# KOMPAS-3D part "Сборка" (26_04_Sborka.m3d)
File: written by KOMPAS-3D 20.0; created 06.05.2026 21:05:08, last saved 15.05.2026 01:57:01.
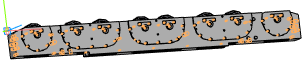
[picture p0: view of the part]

Document properties: Автор: taras; Полное имя файла: E:\test_kompas\all_v18\26_04_Sborka.m3d

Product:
- Part/product: Сборка
    Масса: 400.156
  - Component [standard]: Винт М12-6gx20 ГОСТ 11738-84  | qty 16  | pos. 31  | Масса: 0.03416; Раздел спецификации: Стандартные изделия; Рассекать на разрезах: no
  - Component [standard]: Болт М16-6gx170 ГОСТ 7795-70  | qty 6  | pos. 30  | Масса: 0.2633; Раздел спецификации: Стандартные изделия; Рассекать на разрезах: no
  - Component [standard]: Подшипник 318 ГОСТ 8338-75  | qty 7  | pos. 29  | Масса: 4.954; Раздел спецификации: Стандартные изделия; additional columns: 318
  - Component [detail]: Деталь  | pos. 28  | Масса: 0.134151; source file: ..\all_v22\Planka_rigelnaya (1).m3d
  - Component [detail]: Деталь  | pos. 27  | Масса: 0.134151; source file: ..\all_v22\Planka_rigelnaya (1).m3d
  - Component [detail]: Деталь  | pos. 26  | Масса: 0.134151; source file: ..\all_v22\Planka_rigelnaya (1).m3d
  - Component [detail]: Деталь  | pos. 25  | Масса: 0.134151; source file: ..\all_v22\Planka_rigelnaya (1).m3d
  - Component [detail]: Деталь  | pos. 24  | Масса: 0.134151; source file: ..\all_v22\Planka_rigelnaya (1).m3d
  - Component [detail]: Деталь  | pos. 23  | Масса: 0.134151; source file: ..\all_v22\Planka_rigelnaya (1).m3d
  - Component [detail]: Деталь  | pos. 22  | Масса: 0.134151; source file: ..\all_v22\Planka_rigelnaya (1).m3d
  - Component [detail]: Деталь  | pos. 21  | Масса: 0.134151; source file: ..\all_v22\Planka_rigelnaya (1).m3d
  - Component [detail]: Деталь  | pos. 20  | Масса: 2.04624; source file: ..\all_v22\Planka_rigelnaya (1).m3d
  - Component [detail]: Деталь  | pos. 19  | Масса: 2.04624; source file: ..\all_v22\Planka_rigelnaya (1).m3d
  - Component [standard]: Винт М10-6gx20 ГОСТ 11738-84  | qty 31  | pos. 17  | Масса: 0.02351; Раздел спецификации: Стандартные изделия; Рассекать на разрезах: no
  - Component [detail]: Деталь  | pos. 16  | Масса: 2.04624; source file: ..\all_v22\Planka_rigelnaya (1).m3d
  - Component [detail]: Деталь  | pos. 15  | Масса: 9.68884; source file: ..\all_v22\Planka_rigelnaya (1).m3d
  - Component [detail]: Деталь  | pos. 14  | Масса: 2.04624; source file: ..\all_v22\Planka_rigelnaya (1).m3d
  - Component [detail]: Деталь  | pos. 13  | Масса: 2.04624; source file: ..\all_v22\Planka_rigelnaya (1).m3d
  - Component [detail]: Деталь  | pos. 12  | Масса: 19.9484; source file: ..\all_v22\Planka_rigelnaya (1).m3d
  - Component [detail]: Деталь  | pos. 8  | Масса: 2.04624; source file: ..\all_v22\Planka_rigelnaya (1).m3d
  - Component [detail]: Деталь  | pos. 7  | Масса: 2.04624; source file: ..\all_v22\Planka_rigelnaya (1).m3d
  - Component [detail]: Деталь  | pos. 6  | Масса: 2.04624; source file: ..\all_v22\Planka_rigelnaya (1).m3d
  - Component [detail]: Деталь  | pos. 5  | Масса: 9.68884; source file: ..\all_v22\Planka_rigelnaya (1).m3d
  - Component [detail]: Деталь  | pos. 4  | Масса: 21.9342; source file: ..\all_v22\Planka_rigelnaya (1).m3d
  - Component [detail]: Деталь  | pos. 3  | Масса: 21.9342; source file: ..\all_v22\Planka_rigelnaya (1).m3d
  - Component [detail]: Деталь  | pos. 2  | Масса: 261.985; source file: ..\all_v22\Planka_rigelnaya (1).m3d
  - unknown [detail]: Деталь
      Масса: 261.985
      Организация: TMK
  - unknown [standard]: Винт М12-6gx20 ГОСТ 11738-84  | pos. 31
      Масса: 0.03416
      Раздел спецификации: Стандартные изделия
      Рассекать на разрезах: no
  - unknown [standard]: Болт М16-6gx170 ГОСТ 7795-70  | pos. 30
      Масса: 0.2633
      Раздел спецификации: Стандартные изделия
      Рассекать на разрезах: no
  - unknown [standard]: Подшипник 318 ГОСТ 8338-75  | pos. 29
      Масса: 4.954
      Раздел спецификации: Стандартные изделия
      additional columns: 318
  - unknown [standard]: Винт М10-6gx20 ГОСТ 11738-84  | pos. 17
      Масса: 0.02351
      Раздел спецификации: Стандартные изделия
      Рассекать на разрезах: no

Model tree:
1. Отверстие:2  (with: Вырезать элемент выдавливания:22, Элемент выдавливания:2, Вырезать элемент выдавливания:16, Элемент выдавливания:5, Фаска:1, Элемент выдавливания:3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)  (labels: Скругление:2; Скругление:1; Скругление:2; Скругление:2)
     Ориентация = 2

Referenced files in C:\Program Files\ASCON\KOMPAS-3D v20\Libs\PartLib\DATA\VAULT\methods\kompas\3d\: PLib_Screw_GOST_11738_1500.m3d, PLib_Bolt_1_900.m3d
Referenced files in C:\Program Files\ASCON\KOMPAS-3D v22\Libs\PolynomLib\DATA\vault\Methods\Kompas\3D\: PLib_Screw_GOST_11738_1500.m3d, PLib_Bolt_1_900.m3d
Referenced files in C:\Program Files\ASCON\KOMPAS-3D v20\Libs\PartLib\DATA\VAULT\methods\kompas\3d\Bearings\8338_75\: PLib_Bearing_GOST_8338_75_712.a3d
Referenced files in C:\Program Files\ASCON\KOMPAS-3D v22\Libs\PolynomLib\DATA\vault\Methods\Kompas\3D\Bearings\8338_75\: PLib_Bearing_GOST_8338_75_712.a3d
Referenced files in E:\test_kompas\all_v20\: 3.1.8 дет.45 Балка(оригинал) (1).m3d, 3.1.8  дет.46.2 Крышка балки (2).m3d, Крышка балки 1 окончательная (3).m3d, 3.1.8 дет.74 Ось кронштейна крепления опорного ролика(новый блок) (1).m3d, 05.04 крышка200.m3d, Planka_rigelnaya (1).m3d
Referenced files in C:\Program Files\ASCON\KOMPAS-3D v23 Study\Libs\PolynomLib\DATA\vault\Methods\Kompas\3D\: PLib_Screw_GOST_11738_1500.m3d, PLib_Bolt_1_900.m3d
Referenced files in C:\Program Files\ASCON\KOMPAS-3D v23 Study\Libs\PolynomLib\DATA\vault\Methods\Kompas\3D\Bearings\8338_75\: PLib_Bearing_GOST_8338_75_712.a3d
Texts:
  BOSimple***PART:419c87c2-70e2-98da-c2de-5eacb226740c***SHORTLOC:Root±30±20±10±80±10±GMC90[Нет;Без покрытия;Без указания материала;1,5;-;20;10]
  BOSimple***PART:61ab3e34-d848-86f0-c4aa-2b99c9f755c6***SHORTLOC:Root±Pac-16±Pac10±GMC20±GMC30±GMC10±GMC24[90;190;43]
  BOSimple***PART:9b7fe62b-1d30-3d6e-6be6-01a0e1891a36***SHORTLOC:Root±30±20±10±80±10±©{}30±©{BASE}130±190[Нет;Без покрытия;Без указания материала;170;16;22;2;-]
  BOSimple***PART:d3aa4c40-18a1-862e-ff95-3d42db175957***SHORTLOC:Root±30±20±10±80±10±GMC90[Нет;Без покрытия;Без указания материала;1,75;-;20;12]
  Деталь (1)
  Деталь (2)
  Деталь (3)
  Деталь (4)
  Деталь (5)
  Деталь (6)
  Винт М10-6gx20 ГОСТ 11738-84 (1)
  Винт М10-6gx20 ГОСТ 11738-84 (2)
  Винт М10-6gx20 ГОСТ 11738-84 (3)
  Винт М10-6gx20 ГОСТ 11738-84 (4)
  Винт М10-6gx20 ГОСТ 11738-84 (5)
  Винт М10-6gx20 ГОСТ 11738-84 (6)
  Винт М10-6gx20 ГОСТ 11738-84 (7)
  Винт М10-6gx20 ГОСТ 11738-84 (8)
  Винт М10-6gx20 ГОСТ 11738-84 (9)
  Винт М10-6gx20 ГОСТ 11738-84 (10)
  Винт М10-6gx20 ГОСТ 11738-84 (11)
  Винт М10-6gx20 ГОСТ 11738-84 (12)
  Винт М10-6gx20 ГОСТ 11738-84 (13)
  Винт М10-6gx20 ГОСТ 11738-84 (14)
  Винт М10-6gx20 ГОСТ 11738-84 (15)
  Винт М10-6gx20 ГОСТ 11738-84 (16)
  Винт М10-6gx20 ГОСТ 11738-84 (17)
  Винт М10-6gx20 ГОСТ 11738-84 (18)
  Винт М10-6gx20 ГОСТ 11738-84 (19)
  Винт М10-6gx20 ГОСТ 11738-84 (20)
  Винт М10-6gx20 ГОСТ 11738-84 (21)
  Винт М10-6gx20 ГОСТ 11738-84 (22)
  Винт М10-6gx20 ГОСТ 11738-84 (23)
  Винт М10-6gx20 ГОСТ 11738-84 (24)
  Винт М10-6gx20 ГОСТ 11738-84 (25)
  Винт М10-6gx20 ГОСТ 11738-84 (26)
  Винт М10-6gx20 ГОСТ 11738-84 (27)
  Винт М10-6gx20 ГОСТ 11738-84 (28)
  Винт М10-6gx20 ГОСТ 11738-84 (29)
  Винт М10-6gx20 ГОСТ 11738-84 (30)
  Винт М10-6gx20 ГОСТ 11738-84 (31)
  Деталь (7)
  Деталь (8)
  Подшипник 318 ГОСТ 8338-75 (1)
  Подшипник 318 ГОСТ 8338-75 (2)
  Подшипник 318 ГОСТ 8338-75 (3)
  Подшипник 318 ГОСТ 8338-75 (4)
  Подшипник 318 ГОСТ 8338-75 (5)
  Подшипник 318 ГОСТ 8338-75 (6)
  Подшипник 318 ГОСТ 8338-75 (7)
  Болт М16-6gx170 ГОСТ 7795-70 (1)
  hole1
  hole2
  Болт М16-6gx170 ГОСТ 7795-70 (2)
  Болт М16-6gx170 ГОСТ 7795-70 (3)
  Болт М16-6gx170 ГОСТ 7795-70 (4)
  Болт М16-6gx170 ГОСТ 7795-70 (5)
  Болт М16-6gx170 ГОСТ 7795-70 (6)
  Винт М12-6gx20 ГОСТ 11738-84 (1)
  Винт М12-6gx20 ГОСТ 11738-84 (2)
  Винт М12-6gx20 ГОСТ 11738-84 (3)
  Винт М12-6gx20 ГОСТ 11738-84 (4)
  Винт М12-6gx20 ГОСТ 11738-84 (5)
  Винт М12-6gx20 ГОСТ 11738-84 (6)
  Винт М12-6gx20 ГОСТ 11738-84 (7)
  Винт М12-6gx20 ГОСТ 11738-84 (8)
  Винт М12-6gx20 ГОСТ 11738-84 (9)
  Винт М12-6gx20 ГОСТ 11738-84 (10)
  Винт М12-6gx20 ГОСТ 11738-84 (11)
  Винт М12-6gx20 ГОСТ 11738-84 (12)
  Винт М12-6gx20 ГОСТ 11738-84 (13)
  Винт М12-6gx20 ГОСТ 11738-84 (14)
  Винт М12-6gx20 ГОСТ 11738-84 (15)
  Винт М12-6gx20 ГОСТ 11738-84 (16)
  Радус под головкой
